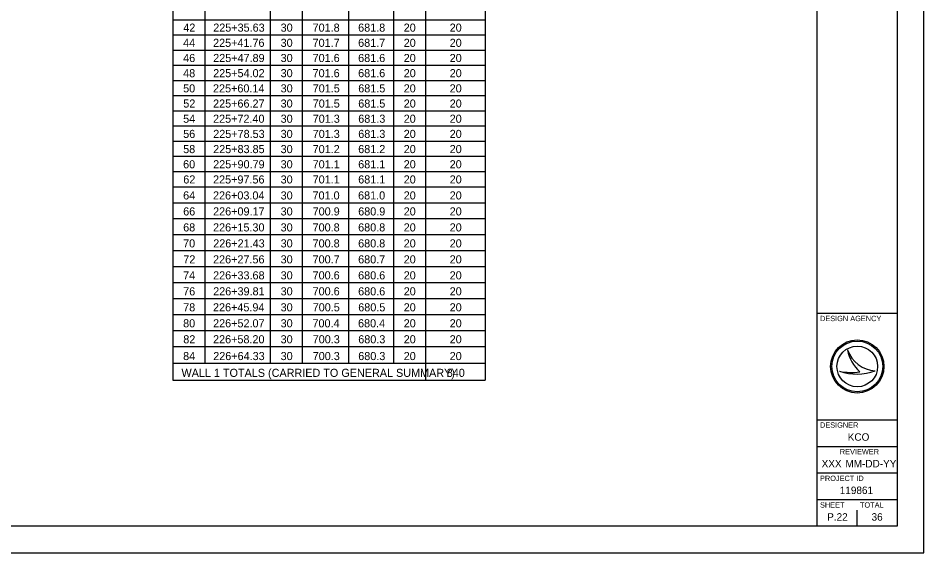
# Model space of a CAD drawing. Extents: x 0 to 34, y 0 to 22.
# Drawn here: x 17 to 34, y 0 to 10.04 of the extents above; entities that cross this region are included whole.
import ezdxf

# ---------------------------------------------------------------- set-up
doc = ezdxf.new("R2010")
doc.units = 0
for name, color, linetype in [('SH_Border', 7, 'Continuous'), ('SH_Cut_Line', 7, 'Continuous'), ('SH_Data', 7, 'Continuous'), ('SH_Text', 7, 'Continuous')]:
    doc.layers.add(name, color=color, linetype=linetype)

msp = doc.modelspace()

# ---------------------------------------------------------------- linework, layer by layer
at = {"layer": 'SH_Border'}
for p, q in [((32, 0.5), (32, 21.5)), ((32, 4.5), (33.5, 4.5)), ((32, 2.5), (33.5, 2.5)), ((32, 2), (33.5, 2)), ((32, 1.5), (33.5, 1.5)), ((32, 1), (33.5, 1))]:
    msp.add_line(p, q, dxfattribs=at)
msp.add_lwpolyline([(1.5, 21.5), (33.5, 21.5), (33.5, 0.5), (1.5, 0.5)], close=True, dxfattribs=at)
at = {"layer": 'SH_Cut_Line'}
msp.add_lwpolyline([(0, 0), (34, 0), (34, 22), (0, 22)], close=True, dxfattribs=at)
at = {"layer": 'SH_Data'}
for p, q in [((32.567, 3.81), (32.567, 3.81)), ((32.417, 3.41), (32.417, 3.41)), ((32.75, 3.5), (32.75, 3.5)), ((33.087, 3.419), (33.087, 3.419)), ((32.75, 0.5), (32.75, 0.8)), ((32.375, 0.675), (32.375, 0.675))]:
    msp.add_line(p, q, dxfattribs=at)
for radius in [0.5, 0.477, 0.477, 0.382]:
    msp.add_circle((32.75, 3.5), radius, dxfattribs=at)
for centre, radius, start, end in [((33.116, 3.998), 0.58, 198.9257, 198.9319), ((33.347, 3.97), 0.796, 191.6379, 191.6421), ((33.116, 3.998), 0.58, 198.9319, 267.1657), ((33.347, 3.97), 0.796, 191.6421, 226.0947), ((32.739, 4.37), 1.013, 251.4576, 290.0832), ((32.648, 4.654), 1.266, 259.4964, 259.4995), ((32.739, 4.37), 1.013, 251.4527, 251.4576), ((32.648, 4.654), 1.266, 259.4995, 276.6672)]:
    msp.add_arc(centre, radius, start, end, dxfattribs=at)
at = {"layer": 'SH_Text'}
for p, q in [((19.903, 18.934), (19.903, 3.244)), ((25.768, 18.934), (25.768, 3.244)), ((20.503, 18.619), (20.503, 3.559)), ((21.733, 18.619), (21.733, 3.559)), ((22.333, 18.619), (22.333, 3.559)), ((23.203, 18.619), (23.203, 3.559)), ((24.043, 18.619), (24.043, 3.559)), ((24.643, 18.619), (24.643, 3.244)), ((19.903, 10.009), (25.768, 10.009)), ((19.903, 9.724), (25.768, 9.724)), ((19.903, 9.439), (25.768, 9.439)), ((19.903, 9.154), (25.768, 9.154)), ((19.903, 8.869), (25.768, 8.869)), ((19.903, 8.584), (25.768, 8.584)), ((19.903, 8.299), (25.768, 8.299)), ((19.903, 8.014), (25.768, 8.014)), ((19.903, 7.729), (25.768, 7.729)), ((19.903, 7.444), (25.768, 7.444)), ((19.903, 7.159), (25.768, 7.159)), ((19.903, 6.874), (25.768, 6.874)), ((19.903, 6.574), (25.768, 6.574)), ((19.903, 6.274), (25.768, 6.274)), ((19.903, 5.974), (25.768, 5.974)), ((19.903, 5.674), (25.768, 5.674)), ((19.903, 5.374), (25.768, 5.374)), ((19.903, 5.074), (25.768, 5.074)), ((19.903, 4.774), (25.768, 4.774)), ((19.903, 4.474), (25.768, 4.474)), ((19.903, 4.174), (25.768, 4.174)), ((19.903, 3.874), (25.768, 3.874)), ((19.903, 3.559), (25.768, 3.559)), ((19.903, 3.244), (25.768, 3.244))]:
    msp.add_line(p, q, dxfattribs=at)

# ---------------------------------------------------------------- texts
at = {"layer": 'SH_Data'}
for s, height, p in [('DESIGN AGENCY', 0.1, (32.05, 4.35)), ('DESIGNER', 0.1, (32.05, 2.35)), ('KCO', 0.14, (32.571, 2.105)), ('REVIEWER', 0.1, (32.422, 1.85)), ('XXX', 0.14, (32.081, 1.605)), ('MM-DD-YY', 0.14, (32.527, 1.605)), ('PROJECT ID', 0.1, (32.05, 1.35)), ('119861', 0.14, (32.421, 1.105)), ('SHEET', 0.1, (32.05, 0.85)), ('TOTAL', 0.1, (32.8, 0.85)), ('P.22', 0.14, (32.185, 0.605)), ('36', 0.14, (33.018, 0.605))]:
    msp.add_text(s, height=height, dxfattribs=at).set_placement(p)
at = {"layer": 'SH_Text'}
for s, p in [('42', (20.1, 9.784)), ('225+35.63', (20.662, 9.784)), ('30', (21.927, 9.784)), ('701.8', (22.527, 9.784)), ('681.8', (23.382, 9.784)), ('20', (24.237, 9.784)), ('20', (25.1, 9.784)), ('44', (20.097, 9.499)), ('225+41.76', (20.659, 9.499)), ('30', (21.927, 9.499)), ('701.7', (22.527, 9.499)), ('681.7', (23.382, 9.499)), ('20', (24.237, 9.499)), ('20', (25.1, 9.499)), ('46', (20.098, 9.214)), ('225+47.89', (20.661, 9.214)), ('30', (21.927, 9.214)), ('701.6', (22.527, 9.214)), ('681.6', (23.382, 9.214)), ('20', (24.237, 9.214)), ('20', (25.1, 9.214)), ('48', (20.098, 8.929)), ('225+54.02', (20.661, 8.929)), ('30', (21.927, 8.929)), ('701.6', (22.527, 8.929)), ('681.6', (23.382, 8.929)), ('20', (24.237, 8.929)), ('20', (25.1, 8.929)), ('50', (20.097, 8.644)), ('225+60.14', (20.658, 8.644)), ('30', (21.927, 8.644)), ('701.5', (22.529, 8.644)), ('681.5', (23.384, 8.644)), ('20', (24.237, 8.644)), ('20', (25.1, 8.644)), ('52', (20.1, 8.359)), ('225+66.27', (20.66, 8.359)), ('30', (21.927, 8.359)), ('701.5', (22.529, 8.359)), ('681.5', (23.384, 8.359)), ('20', (24.237, 8.359)), ('20', (25.1, 8.359)), ('54', (20.097, 8.074)), ('225+72.40', (20.659, 8.074)), ('30', (21.927, 8.074)), ('701.3', (22.529, 8.074)), ('681.3', (23.384, 8.074)), ('20', (24.237, 8.074)), ('20', (25.1, 8.074)), ('56', (20.098, 7.789)), ('225+78.53', (20.662, 7.789)), ('30', (21.927, 7.789)), ('701.3', (22.529, 7.789)), ('681.3', (23.384, 7.789)), ('20', (24.237, 7.789)), ('20', (25.1, 7.789)), ('58', (20.098, 7.504)), ('225+83.85', (20.661, 7.504)), ('30', (21.927, 7.504)), ('701.2', (22.528, 7.504)), ('681.2', (23.383, 7.504)), ('20', (24.237, 7.504)), ('20', (25.1, 7.504)), ('60', (20.097, 7.219)), ('225+90.79', (20.661, 7.219)), ('30', (21.927, 7.219)), ('701.1', (22.528, 7.219)), ('681.1', (23.383, 7.219)), ('20', (24.237, 7.219)), ('20', (25.1, 7.219)), ('62', (20.1, 6.934)), ('225+97.56', (20.659, 6.934)), ('30', (21.927, 6.934)), ('701.1', (22.528, 6.934)), ('681.1', (23.383, 6.934)), ('20', (24.237, 6.934)), ('20', (25.1, 6.934)), ('64', (20.097, 6.634)), ('226+03.04', (20.658, 6.634)), ('30', (21.927, 6.634)), ('701.0', (22.526, 6.634)), ('681.0', (23.381, 6.634)), ('20', (24.237, 6.634)), ('20', (25.1, 6.634)), ('66', (20.098, 6.334)), ('226+09.17', (20.66, 6.334)), ('30', (21.927, 6.334)), ('700.9', (22.528, 6.334)), ('680.9', (23.383, 6.334)), ('20', (24.237, 6.334)), ('20', (25.1, 6.334)), ('68', (20.098, 6.034)), ('226+15.30', (20.659, 6.034)), ('30', (21.927, 6.034)), ('700.8', (22.527, 6.034)), ('680.8', (23.382, 6.034)), ('20', (24.237, 6.034)), ('20', (25.1, 6.034)), ('70', (20.097, 5.734)), ('226+21.43', (20.662, 5.734)), ('30', (21.927, 5.734)), ('700.8', (22.527, 5.734)), ('680.8', (23.382, 5.734)), ('20', (24.237, 5.734)), ('20', (25.1, 5.734)), ('72', (20.1, 5.434)), ('226+27.56', (20.659, 5.434)), ('30', (21.927, 5.434)), ('700.7', (22.527, 5.434)), ('680.7', (23.382, 5.434)), ('20', (24.237, 5.434)), ('20', (25.1, 5.434)), ('74', (20.097, 5.134)), ('226+33.68', (20.66, 5.134)), ('30', (21.927, 5.134)), ('700.6', (22.527, 5.134)), ('680.6', (23.382, 5.134)), ('20', (24.237, 5.134)), ('20', (25.1, 5.134)), ('76', (20.098, 4.834)), ('226+39.81', (20.661, 4.834)), ('30', (21.927, 4.834)), ('700.6', (22.527, 4.834)), ('680.6', (23.382, 4.834)), ('20', (24.237, 4.834)), ('20', (25.1, 4.834)), ('78', (20.098, 4.534)), ('226+45.94', (20.658, 4.534)), ('30', (21.927, 4.534)), ('700.5', (22.529, 4.534)), ('680.5', (23.384, 4.534)), ('20', (24.237, 4.534)), ('20', (25.1, 4.534)), ('80', (20.097, 4.234)), ('226+52.07', (20.66, 4.234)), ('30', (21.927, 4.234)), ('700.4', (22.525, 4.234)), ('680.4', (23.38, 4.234)), ('20', (24.237, 4.234)), ('20', (25.1, 4.234)), ('82', (20.1, 3.934)), ('226+58.20', (20.659, 3.934)), ('30', (21.927, 3.934)), ('700.3', (22.529, 3.934)), ('680.3', (23.384, 3.934)), ('20', (24.237, 3.934)), ('20', (25.1, 3.934)), ('84', (20.097, 3.619)), ('226+64.33', (20.662, 3.619)), ('30', (21.927, 3.619)), ('700.3', (22.529, 3.619)), ('680.3', (23.384, 3.619)), ('20', (24.237, 3.619)), ('20', (25.1, 3.619)), ('WALL 1 TOTALS (CARRIED TO GENERAL SUMMARY)', (20.066, 3.304)), ('840', (25.045, 3.304))]:
    msp.add_text(s, height=0.1518, dxfattribs=at).set_placement(p)

doc.saveas('drawing.dxf')
